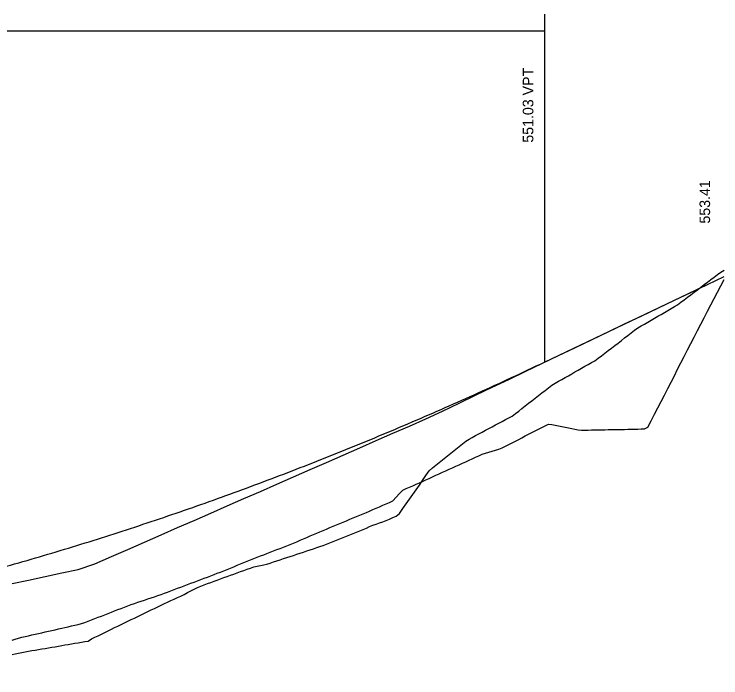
# Model space of a CAD drawing. Extents: x 1733822 to 1737718, y 1214897 to 1219897.
# Drawn here: x 1735609.6 to 1735823, y 1218311.8 to 1218512.1 of the extents above; entities that cross this region are included whole.
import ezdxf

# ---------------------------------------------------------------- set-up
doc = ezdxf.new("R2010")
doc.units = 0
for name, color, linetype in [('RD_DDB_Profile_EX', 7, 'Continuous'), ('RD_DDB_Profile_Lbl', 7, 'Continuous'), ('RD_DDB_Profile_PR', 7, 'Continuous'), ('RD_DDB_StripGrade', 7, 'Continuous'), ('RD_DDB_VCLbl', 7, 'Continuous'), ('RD_Sketch1', 7, 'Continuous'), ('RD_Sketch2', 7, 'Continuous')]:
    doc.layers.add(name, color=color, linetype=linetype)

msp = doc.modelspace()

# ---------------------------------------------------------------- linework, layer by layer
at = {"layer": 'RD_DDB_Profile_EX'}
msp.add_lwpolyline([(1735608.97, 1218340.21), (1735613.97, 1218341.28), (1735618.97, 1218342.35), (1735623.97, 1218343.41), (1735628.97, 1218344.48), (1735633.97, 1218346.15), (1735638.97, 1218348.34), (1735643.97, 1218350.53), (1735648.97, 1218352.71), (1735653.97, 1218354.9), (1735658.97, 1218357.09), (1735663.97, 1218359.28), (1735668.97, 1218361.47), (1735673.97, 1218363.66), (1735678.97, 1218365.85), (1735683.97, 1218368.04), (1735688.97, 1218370.23), (1735693.97, 1218372.42), (1735698.97, 1218374.61), (1735703.97, 1218376.8), (1735708.97, 1218378.99), (1735713.97, 1218381.18), (1735718.97, 1218383.37), (1735723.97, 1218385.56), (1735728.97, 1218387.75), (1735733.97, 1218389.94), (1735738.97, 1218392.29), (1735743.97, 1218394.67), (1735748.97, 1218397.06), (1735753.97, 1218399.45), (1735758.97, 1218401.84), (1735763.97, 1218404.22), (1735768.97, 1218406.61), (1735773.97, 1218409), (1735778.97, 1218411.39), (1735783.97, 1218413.77), (1735788.97, 1218416.16), (1735793.97, 1218418.55), (1735798.97, 1218420.94), (1735803.97, 1218423.32), (1735808.97, 1218425.71), (1735813.97, 1218428.1), (1735818.97, 1218430.48), (1735823.97, 1218432.87)], dxfattribs=at)
at = {"layer": 'RD_DDB_Profile_PR'}
msp.add_line((1735769.77, 1218407.06), (1735819.77, 1218430.85), dxfattribs=at)
msp.add_spline([(1735269.77, 1218317.64), (1735279.77, 1218316.52), (1735289.77, 1218315.51), (1735299.77, 1218314.63), (1735309.77, 1218313.86), (1735319.77, 1218313.22), (1735329.77, 1218312.69), (1735339.77, 1218312.28), (1735349.77, 1218311.99), (1735359.77, 1218311.81), (1735369.77, 1218311.76), (1735379.77, 1218311.83), (1735389.77, 1218312.01), (1735399.77, 1218312.31), (1735409.77, 1218312.74), (1735419.77, 1218313.28), (1735429.77, 1218313.94), (1735439.77, 1218314.72), (1735449.77, 1218315.61), (1735459.77, 1218316.63), (1735469.77, 1218317.76), (1735479.77, 1218319.02), (1735489.77, 1218320.39), (1735499.77, 1218321.88), (1735509.77, 1218323.49), (1735519.77, 1218325.22), (1735529.77, 1218327.07), (1735539.77, 1218329.04), (1735549.77, 1218331.12), (1735559.77, 1218333.33), (1735569.77, 1218335.65), (1735579.77, 1218338.09), (1735589.77, 1218340.65), (1735599.77, 1218343.33), (1735609.77, 1218346.13), (1735619.77, 1218349.05), (1735629.77, 1218352.08), (1735639.77, 1218355.24), (1735649.77, 1218358.51), (1735659.77, 1218361.9), (1735669.77, 1218365.41), (1735679.77, 1218369.04), (1735689.77, 1218372.79), (1735699.77, 1218376.66), (1735709.77, 1218380.65), (1735719.77, 1218384.75), (1735729.77, 1218388.98), (1735739.77, 1218393.32), (1735749.77, 1218397.78), (1735759.77, 1218402.36), (1735769.77, 1218407.06)], degree=3, dxfattribs=at)
at = {"layer": 'RD_DDB_VCLbl'}
for p, q in [((1735769.77, 1218512.06), (1735769.77, 1218407.06)), ((1735269.77, 1218507.06), (1735769.77, 1218507.06))]:
    msp.add_line(p, q, dxfattribs=at)
at = {"layer": 'RD_Sketch1'}
for points in [[(1735815.97, 1218428.9), (1735816.97, 1218429.66), (1735817.97, 1218430.42), (1735818.97, 1218431.17), (1735819.97, 1218431.93), (1735820.97, 1218432.69), (1735821.97, 1218433.45), (1735822.97, 1218434.2), (1735823.97, 1218434.81)], [(1735715.97, 1218356.98), (1735716.97, 1218357.39), (1735717.97, 1218357.79), (1735718.97, 1218358.17), (1735719.97, 1218358.52), (1735720.97, 1218358.87), (1735721.97, 1218359.23), (1735722.97, 1218359.66), (1735723.97, 1218360.12), (1735724.97, 1218360.59), (1735725.97, 1218361.4), (1735726.97, 1218362.82), (1735727.97, 1218364.24), (1735728.97, 1218365.67), (1735729.97, 1218367.09), (1735730.97, 1218368.51), (1735731.97, 1218369.94), (1735732.97, 1218371.36), (1735733.97, 1218372.78), (1735734.97, 1218374.2), (1735735.97, 1218375.17), (1735736.97, 1218375.97), (1735737.97, 1218376.77), (1735738.97, 1218377.56), (1735739.97, 1218378.36), (1735740.97, 1218379.16), (1735741.97, 1218379.96), (1735742.97, 1218380.76), (1735743.97, 1218381.56), (1735744.97, 1218382.36), (1735745.97, 1218383.15), (1735746.97, 1218383.77), (1735747.97, 1218384.31), (1735748.97, 1218384.85), (1735749.97, 1218385.39), (1735750.97, 1218385.93), (1735751.97, 1218386.46), (1735752.97, 1218387), (1735753.97, 1218387.54), (1735754.97, 1218388.08), (1735755.97, 1218388.62), (1735756.97, 1218389.16), (1735757.97, 1218389.7), (1735758.97, 1218390.24), (1735759.97, 1218390.78), (1735760.97, 1218391.51), (1735761.97, 1218392.29), (1735762.97, 1218393.07), (1735763.97, 1218393.85), (1735764.97, 1218394.63), (1735765.97, 1218395.41), (1735766.97, 1218396.19), (1735767.97, 1218396.97), (1735768.97, 1218397.75), (1735769.97, 1218398.53), (1735770.97, 1218399.31), (1735771.97, 1218400.09), (1735772.97, 1218400.69), (1735773.97, 1218401.26), (1735774.97, 1218401.82), (1735775.97, 1218402.39), (1735776.97, 1218402.95), (1735777.97, 1218403.52), (1735778.97, 1218404.08), (1735779.97, 1218404.65), (1735780.97, 1218405.21), (1735781.97, 1218405.78), (1735782.97, 1218406.34), (1735783.97, 1218406.91), (1735784.97, 1218407.47), (1735785.97, 1218408.21), (1735786.97, 1218408.98), (1735787.97, 1218409.74), (1735788.97, 1218410.51), (1735789.97, 1218411.28), (1735790.97, 1218412.04), (1735791.97, 1218412.81), (1735792.97, 1218413.58), (1735793.97, 1218414.34), (1735794.97, 1218415.11), (1735795.97, 1218415.88), (1735796.97, 1218416.64), (1735797.97, 1218417.37), (1735798.97, 1218417.96), (1735799.97, 1218418.54), (1735800.97, 1218419.12), (1735801.97, 1218419.71), (1735802.97, 1218420.29), (1735803.97, 1218420.87), (1735804.97, 1218421.46), (1735805.97, 1218422.04), (1735806.97, 1218422.62), (1735807.97, 1218423.21), (1735808.97, 1218423.79), (1735809.97, 1218424.37), (1735810.97, 1218425.12), (1735811.97, 1218425.87), (1735812.97, 1218426.63), (1735813.97, 1218427.39), (1735814.97, 1218428.15), (1735815.97, 1218428.9)], [(1735615.97, 1218320.15), (1735616.97, 1218320.32), (1735617.97, 1218320.49), (1735618.97, 1218320.66), (1735619.97, 1218320.83), (1735620.97, 1218321), (1735621.97, 1218321.17), (1735622.97, 1218321.35), (1735623.97, 1218321.52), (1735624.97, 1218321.69), (1735625.97, 1218321.86), (1735626.97, 1218322.03), (1735627.97, 1218322.2), (1735628.97, 1218322.37), (1735629.97, 1218322.54), (1735630.97, 1218322.71), (1735631.97, 1218322.88), (1735632.97, 1218323.51), (1735633.97, 1218324), (1735634.97, 1218324.48), (1735635.97, 1218324.97), (1735636.97, 1218325.45), (1735637.97, 1218325.94), (1735638.97, 1218326.42), (1735639.97, 1218326.91), (1735640.97, 1218327.39), (1735641.97, 1218327.88), (1735642.97, 1218328.36), (1735643.97, 1218328.85), (1735644.97, 1218329.33), (1735645.97, 1218329.82), (1735646.97, 1218330.3), (1735647.97, 1218330.79), (1735648.97, 1218331.27), (1735649.97, 1218331.76), (1735650.97, 1218332.24), (1735651.97, 1218332.73), (1735652.97, 1218333.21), (1735653.97, 1218333.7), (1735654.97, 1218334.18), (1735655.97, 1218334.64), (1735656.97, 1218335.06), (1735657.97, 1218335.49), (1735658.97, 1218335.96), (1735659.97, 1218336.45), (1735660.97, 1218336.96), (1735661.97, 1218337.48), (1735662.97, 1218337.99), (1735663.97, 1218338.5), (1735664.97, 1218339.02), (1735665.97, 1218339.48), (1735666.97, 1218339.84), (1735667.97, 1218340.2), (1735668.97, 1218340.56), (1735669.97, 1218340.92), (1735670.97, 1218341.28), (1735671.97, 1218341.64), (1735672.97, 1218342), (1735673.97, 1218342.36), (1735674.97, 1218342.72), (1735675.97, 1218343.09), (1735676.97, 1218343.45), (1735677.97, 1218343.81), (1735678.97, 1218344.17), (1735679.97, 1218344.53), (1735680.97, 1218344.89), (1735681.97, 1218345.25), (1735682.97, 1218345.49), (1735683.97, 1218345.68), (1735684.97, 1218345.86), (1735685.97, 1218346.08), (1735686.97, 1218346.41), (1735687.97, 1218346.75), (1735688.97, 1218347.08), (1735689.97, 1218347.41), (1735690.97, 1218347.74), (1735691.97, 1218348.07), (1735692.97, 1218348.4), (1735693.97, 1218348.73), (1735694.97, 1218349.06), (1735695.97, 1218349.39), (1735696.97, 1218349.72), (1735697.97, 1218350.05), (1735698.97, 1218350.38), (1735699.97, 1218350.72), (1735700.97, 1218351.05), (1735701.97, 1218351.38), (1735702.97, 1218351.72), (1735703.97, 1218352.13), (1735704.97, 1218352.53), (1735705.97, 1218352.94), (1735706.97, 1218353.34), (1735707.97, 1218353.74), (1735708.97, 1218354.15), (1735709.97, 1218354.55), (1735710.97, 1218354.96), (1735711.97, 1218355.36), (1735712.97, 1218355.77), (1735713.97, 1218356.17), (1735714.97, 1218356.58), (1735715.97, 1218356.98)], [(1735608.97, 1218318.8), (1735609.97, 1218318.97), (1735610.97, 1218319.18), (1735611.97, 1218319.38), (1735612.97, 1218319.58), (1735613.97, 1218319.79), (1735614.97, 1218319.98), (1735615.97, 1218320.15)]]:
    msp.add_lwpolyline(points, dxfattribs=at)
at = {"layer": 'RD_Sketch2'}
for points in [[(1735813.97, 1218412.67), (1735814.97, 1218414.61), (1735815.97, 1218416.56), (1735816.97, 1218418.5), (1735817.97, 1218420.45), (1735818.97, 1218422.39), (1735819.97, 1218424.33), (1735820.97, 1218426.26), (1735821.97, 1218428.17), (1735822.97, 1218430.09), (1735823.97, 1218432.01)], [(1735713.97, 1218360.86), (1735714.97, 1218361.28), (1735715.97, 1218361.7), (1735716.97, 1218362.11), (1735717.97, 1218362.55), (1735718.97, 1218362.98), (1735719.97, 1218363.42), (1735720.97, 1218363.85), (1735721.97, 1218364.28), (1735722.97, 1218364.72), (1735723.97, 1218365.15), (1735724.97, 1218366.27), (1735725.97, 1218367.42), (1735726.97, 1218368.43), (1735727.97, 1218368.87), (1735728.97, 1218369.31), (1735729.97, 1218369.74), (1735730.97, 1218370.18), (1735731.97, 1218370.62), (1735732.97, 1218371.06), (1735733.97, 1218371.52), (1735734.97, 1218371.97), (1735735.97, 1218372.43), (1735736.97, 1218372.88), (1735737.97, 1218373.34), (1735738.97, 1218373.79), (1735739.97, 1218374.25), (1735740.97, 1218374.7), (1735741.97, 1218375.16), (1735742.97, 1218375.61), (1735743.97, 1218376.07), (1735744.97, 1218376.52), (1735745.97, 1218376.98), (1735746.97, 1218377.43), (1735747.97, 1218377.89), (1735748.97, 1218378.34), (1735749.97, 1218378.8), (1735750.97, 1218379.25), (1735751.97, 1218379.57), (1735752.97, 1218379.86), (1735753.97, 1218380.15), (1735754.97, 1218380.45), (1735755.97, 1218380.74), (1735756.97, 1218381.15), (1735757.97, 1218381.66), (1735758.97, 1218382.18), (1735759.97, 1218382.69), (1735760.97, 1218383.2), (1735761.97, 1218383.72), (1735762.97, 1218384.23), (1735763.97, 1218384.75), (1735764.97, 1218385.26), (1735765.97, 1218385.78), (1735766.97, 1218386.29), (1735767.97, 1218386.81), (1735768.97, 1218387.32), (1735769.97, 1218387.84), (1735770.97, 1218388.35), (1735771.97, 1218388.19), (1735772.97, 1218387.99), (1735773.97, 1218387.79), (1735774.97, 1218387.6), (1735775.97, 1218387.4), (1735776.97, 1218387.2), (1735777.97, 1218387.01), (1735778.97, 1218386.81), (1735779.97, 1218386.61), (1735780.97, 1218386.49), (1735781.97, 1218386.51), (1735782.97, 1218386.53), (1735783.97, 1218386.56), (1735784.97, 1218386.58), (1735785.97, 1218386.6), (1735786.97, 1218386.62), (1735787.97, 1218386.64), (1735788.97, 1218386.66), (1735789.97, 1218386.68), (1735790.97, 1218386.7), (1735791.97, 1218386.72), (1735792.97, 1218386.74), (1735793.97, 1218386.76), (1735794.97, 1218386.78), (1735795.97, 1218386.81), (1735796.97, 1218386.83), (1735797.97, 1218386.85), (1735798.97, 1218386.87), (1735799.97, 1218386.89), (1735800.97, 1218387.4), (1735801.97, 1218389.36), (1735802.97, 1218391.31), (1735803.97, 1218393.25), (1735804.97, 1218395.18), (1735805.97, 1218397.12), (1735806.97, 1218399.06), (1735807.97, 1218401.01), (1735808.97, 1218402.95), (1735809.97, 1218404.9), (1735810.97, 1218406.84), (1735811.97, 1218408.78), (1735812.97, 1218410.73), (1735813.97, 1218412.67)], [(1735613.97, 1218324.49), (1735614.97, 1218324.72), (1735615.97, 1218324.94), (1735616.97, 1218325.17), (1735617.97, 1218325.39), (1735618.97, 1218325.62), (1735619.97, 1218325.85), (1735620.97, 1218326.07), (1735621.97, 1218326.3), (1735622.97, 1218326.52), (1735623.97, 1218326.75), (1735624.97, 1218326.97), (1735625.97, 1218327.2), (1735626.97, 1218327.43), (1735627.97, 1218327.65), (1735628.97, 1218327.88), (1735629.97, 1218328.13), (1735630.97, 1218328.51), (1735631.97, 1218328.89), (1735632.97, 1218329.27), (1735633.97, 1218329.66), (1735634.97, 1218330.04), (1735635.97, 1218330.42), (1735636.97, 1218330.81), (1735637.97, 1218331.19), (1735638.97, 1218331.57), (1735639.97, 1218331.95), (1735640.97, 1218332.34), (1735641.97, 1218332.72), (1735642.97, 1218333.1), (1735643.97, 1218333.49), (1735644.97, 1218333.87), (1735645.97, 1218334.24), (1735646.97, 1218334.58), (1735647.97, 1218334.92), (1735648.97, 1218335.25), (1735649.97, 1218335.59), (1735650.97, 1218335.92), (1735651.97, 1218336.26), (1735652.97, 1218336.59), (1735653.97, 1218336.93), (1735654.97, 1218337.27), (1735655.97, 1218337.65), (1735656.97, 1218338.03), (1735657.97, 1218338.4), (1735658.97, 1218338.78), (1735659.97, 1218339.16), (1735660.97, 1218339.54), (1735661.97, 1218339.92), (1735662.97, 1218340.29), (1735663.97, 1218340.67), (1735664.97, 1218341.05), (1735665.97, 1218341.43), (1735666.97, 1218341.81), (1735667.97, 1218342.18), (1735668.97, 1218342.56), (1735669.97, 1218342.94), (1735670.97, 1218343.32), (1735671.97, 1218343.7), (1735672.97, 1218344.08), (1735673.97, 1218344.45), (1735674.97, 1218344.86), (1735675.97, 1218345.29), (1735676.97, 1218345.73), (1735677.97, 1218346.16), (1735678.97, 1218346.59), (1735679.97, 1218347.02), (1735680.97, 1218347.41), (1735681.97, 1218347.79), (1735682.97, 1218348.17), (1735683.97, 1218348.55), (1735684.97, 1218348.93), (1735685.97, 1218349.31), (1735686.97, 1218349.69), (1735687.97, 1218350.07), (1735688.97, 1218350.45), (1735689.97, 1218350.83), (1735690.97, 1218351.21), (1735691.97, 1218351.59), (1735692.97, 1218351.98), (1735693.97, 1218352.42), (1735694.97, 1218352.85), (1735695.97, 1218353.29), (1735696.97, 1218353.72), (1735697.97, 1218354.15), (1735698.97, 1218354.58), (1735699.97, 1218355), (1735700.97, 1218355.42), (1735701.97, 1218355.84), (1735702.97, 1218356.26), (1735703.97, 1218356.68), (1735704.97, 1218357.09), (1735705.97, 1218357.51), (1735706.97, 1218357.93), (1735707.97, 1218358.35), (1735708.97, 1218358.77), (1735709.97, 1218359.19), (1735710.97, 1218359.6), (1735711.97, 1218360.02), (1735712.97, 1218360.44), (1735713.97, 1218360.86)], [(1735608.97, 1218323.13), (1735609.97, 1218323.42), (1735610.97, 1218323.71), (1735611.97, 1218324), (1735612.97, 1218324.26), (1735613.97, 1218324.49)]]:
    msp.add_lwpolyline(points, dxfattribs=at)

# ---------------------------------------------------------------- texts
at = {"layer": 'RD_DDB_Profile_Lbl'}
msp.add_text('553.41', height=3.2, rotation=90, dxfattribs=at).set_placement((1735819.77, 1218448.85))
at = {"layer": 'RD_DDB_StripGrade'}
msp.add_text('551.03 VPT', height=3.2, rotation=90, dxfattribs=at).set_placement((1735766.4, 1218473.26))

doc.saveas('drawing.dxf')
